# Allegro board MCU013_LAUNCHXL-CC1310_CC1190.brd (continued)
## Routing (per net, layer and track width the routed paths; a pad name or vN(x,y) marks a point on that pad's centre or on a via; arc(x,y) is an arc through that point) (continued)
DIO16_TDO: length 62.1
  TOP w0.15: 34.75,69.75 34.9,69.6 v1(34.9,68.7) U1.26 ; 34.75,69.75 34.75,75.8 35.12,76.17 35.12,76.45 35.45,76.78 35.45,77.5 ; 34.75,69.75 34.75,69.75 34.85,69.65 ; CR8.5 42.67,75.9 43.24,76.47 P5.6 43.24,78.45 42.39,79.3 39.5,79.3 37.7,77.5 35.45,77.5 ; v1(47.7,66.5) 47.7,56.7 46.5,55.5 46.5,49.03 45.7,48.22 R48.2 ; 35.45,77.5 35.44,77.5 P4.4
  L3 w0.15: v1(34.9,68.7) 38.6,68.7 40.8,66.5 v1(47.7,66.5)
DIO17_TDI: length 72.1
  TOP w0.15: R49.2 45.7,45.62 44.7,46.62 44.7,55.4 45.7,56.4 v1(45.7,66) ; v1(38.3,79.8) 38,80.1 33.26,80.1 P4.6 v1(31.78,77.42) ; CR8.3 39.7,74.4 40.9,75.6 43.16,75.6 44.51,76.95 P5.8 44.51,79.19 44,79.7 40.1,79.7 40,79.8 v1(39.6,79.8) ; U1.27 v1(34.4,68.22) 34.4,68.7 34.32,68.78 34.32,75.8 34.82,76.3 34.82,76.65 34.7,76.78 v1(34.7,77.42)
  L3 w0.15: v1(34.4,68.22) 38.47,68.22 40.7,66 v1(45.7,66) ; v1(38.3,79.8) v1(39.6,79.8) ; v1(31.78,77.42) v1(34.7,77.42)
DIO19_CTS: length 23.6
  TOP w0.15: 33.4,65.55 U1.29 v1(33.4,67.8) ; v1(46.55,65.5) 46.97,65.07 v1(46.97,61.2)
  L3 w0.15: v1(46.55,65.5) 40.78,65.5 38.47,67.8 v1(33.4,67.8) ; v1(46.97,61.2) 47.38,61.2 47.74,60.84 J2.7
DIO20_FLASH_CS: length 41.6
  TOP w0.15: v1(33.4,68.7) 32.9,68.2 32.9,66.58 U1.30 32.9,65.55 ; v1(44.8,67.7) v1(44.8,64.7) 44.8,60.75 40.45,56.4 39,56.4 38.3,55.7 38.3,53 38.7,52.6 R11.1 U4.1
  L3 w0.15: v1(33.4,68.7) 34.3,69.6 38.9,69.6 40.8,67.7 v1(44.8,67.7) ; J2.5 48.26,64.7 v1(44.8,64.7)
DIO21: length 62.6
  TOP w0.15: U1.31 32.4,66.5 32.6,66.71 32.6,69.69 32.4,69.9 32.4,74.5 31.9,75 9.6,75 2.7,68.1 2.7,67.85 2.7,67.85 2.7,51.3 3.32,50.68 J1.15
DIO22: length 50.6
  TOP w0.15: 32.3,68.43 32.3,66.83 31.9,66.43 U1.32 ; 32.3,68.43 32.3,69.57 32,69.87 32,73.45 31.05,74.4 10.2,74.4 3.3,67.5 3.3,61.38 J1.9 ; 32.3,68.43 32.3,68.43
DIO23_ANALOG: length 28.5
  TOP w0.15: 7.76,67.3 7.76,67.3 11.3,67.3 12.72,65.88 12.72,65.47 13.07,65.13 28.53,65.13 28.95,65.55 U1.36 ; 7.76,67.3 10.9,67.3 ; 7.76,67.3 J1.3
DIO24_ANALOG: length 30.7
  TOP w0.15: J1.11 7.6,56.98 7.6,64 8.43,64.82 U1.37
DIO25_ANALOG: length 20.6
  TOP w0.15: U1.38 9.87,64.32 J1.6
DIO26_ANALOG: length 22.2
  TOP w0.15: U1.39 10.78,63.82 10.05,63.1 10.05,61.97 J1.8
DIO27_ANALOG: length 24.1
  TOP w0.15: U1.40 10.95,63.32 10.6,62.98 10.6,59.98 J1.10
DIO28_CC1190_HGM: length 30.6
  TOP w0.15: J1.12 10.6,57.44 10.6,58.55 11,58.95 11,62.75 11.28,63.03 28.55,63.03 28.75,62.82 U1.41 ; R66.1 v1(11.9,57)
  L3 w0.15: J1.12 10.16,57 v1(11.9,57)
DIO29_CC1190_LNA_EN: length 32.5
  TOP w0.15: J1.14 10.9,55.2 10.9,58.42 11.39,58.91 11.39,62.54 11.57,62.72 28,62.72 28.4,62.32 U1.42 ; v1(11.78,54.15) R71.1
  L3 w0.15: v1(11.78,54.15) 10.88,54.15 9.95,53.22 J1.14
DIO30_CC1190_PA_EN: length 57.3
  TOP w0.15: U1.43 28.48,61.82 27.9,62.4 27.8,62.4 27.78,62.43 23.52,62.43 23.5,62.4 18.4,62.4 ; 18.4,62.4 v1(18.4,56.6) ; 18.4,62.4 12,62.4 11.69,62.09 11.69,58.79 11.35,58.45 11.35,53.11 J1.16 ; v1(33.8,45.05) 33.8,45.05 34.1,44.75 R81.1
  L3 w0.15: v1(33.8,45.05) 30.95,47.9 27.1,47.9 v1(18.4,56.6)
IRSTN: length 16.5
  TOP w0.15: v1(5.3,109.5) 5.3,107.9 v1(3.5,106.1) ; v1(6.82,109.5) 9.5,109.5 11.2,107.8 11.2,105.5 11.8,104.9 R20.2 14.4,104.9
  L3 w0.15: v1(5.3,109.5) v1(6.82,109.5)
ITCK: length 12.2
  TOP w0.15: U5.100 2,100.6 0.8,101.8 0.8,108.7 v1(2.1,110)
ITDI: length 10.1
  TOP w0.15: v1(3.38,108.7) 2.8,108.12 2.8,106.5 1.44,105.14 1.44,102.01 2.05,101.4 U5.98
ITDO: length 13.2
  TOP w0.15: v1(3.4,111.3) 4.8,109.9 4.8,108.08 1.74,105.01 1.74,102.14 2.08,101.8 U5.97
ITMS: length 9
  TOP w0.15: v1(2.1,107.5) 1.14,106.54 1.14,101.89 2.03,101 3.8,101
LP_RESET: length 17.9
  TOP w0.15: R51.1 51.1,72.3 54.4,69 54.4,60.58 J2.10
USB_DM: length 14.1
  TOP w0.15: v1(8.7,110.9) 7.3,110.9 6.4,110 6.4,104.1 6.5,104 U5.93 ; CR6.5 10.8,112.85 v1(10.75,112.9) J6.2
  L3 w0.15: v1(8.7,110.9) 8.99,111.19 9.06,111.19 10.75,112.88 v1(10.75,112.9)
USB_DP: length 15.5
  TOP w0.15: U5.94 6.1,110.12 7.36,111.38 8.91,111.38 v1(9.4,110.9) ; 11.3,112.19 11.3,112.8 v1(11.4,112.9) J6.3
  L3 w0.15: v1(9.4,110.9) v1(11.4,112.9)
USB_ID: length 14.1
  TOP w0.15: J6.4 v1(12.05,112.9) ; R19.1 5.6,106.68 5.8,106.88 5.8,110.25 7.25,111.7 9.4,111.7 10.1,111 v1(10.8,111) CR6.2
  L3 w0.15: v1(12.05,112.9) 10.8,111.65 v1(10.8,111)
USB_VBUS: length 55.8
  TOP w0.15: R22.2 4.38,86.87 v1(4.6,87.1) ; U7.8 v1(14.7,110.58) ; R152.1 3.69,104.7 3.2,104.21 3.2,103.9 v1(2.6,103.3)
  TOP w0.3: J6.1 v1(10.1,112.9) 10.1,112.87 10.3,112.67 CR6.6 ; C48.1 12.2,111.08 11.7,110.58 U7.1 U7.2
  TOP w0.5: v1(12.2,111.9) C48.1
  L3 w0.5: v1(2.6,103.3) 0.85,103.3 0.75,103.4 ; P4.19 11.86,83.3 7.6,83.3 4.6,86.3 v1(4.6,87.1) 0.75,90.95 0.75,103.4 ; 0.75,103.4 0.75,108.24 1.85,109.34 3.94,109.34 4.7,110.1 11.22,110.1
V-SENSE: length 40.2
  TOP w0.15: v1(21.7,85.1) C53.1 U8.2 ; v1(29.9,85.1) C57.1 U9.2 ; v1(25.7,85.1) C55.1 U10.2
  TOP w0.3: v1(29.9,85.1) 36.7,85.1 37.6,86 38.45,86 38.55,85.9 ; P10.2 48.3,82.76 48.3,84.7 46.47,86.53 P7.1 45.76,87.28 44.94,88.1 39.8,88.1 38.55,86.85 38.55,85.9 ; 38.55,85.9 CR7.8
  L3 w0.3: v1(21.7,85.1) v1(25.7,85.1) 26.99,85.1 27.09,85 27.51,85 27.72,85.21 29.09,85.21 29.2,85.1 v1(29.9,85.1)
XDS_RESET: length 11.5
  TOP w0.15: U10.1 23.78,84.7 23.51,84.97 U10.6 v1(23.51,87.7) ; v1(22.8,89.7) 21.8,90.7 21.8,91.69 21.3,92.19 R58.1 U5.40
  L3 w0.15: v1(23.51,87.7) 23.79,87.99 23.79,89.4 23.5,89.7 v1(22.8,89.7)
XDS_RESET_LS: length 62.5
  TOP w0.15: U10.15 23.51,83.49 v1(24,83) 24,82.6 24.16,82.44 P4.11 ; 17.6,114.3 R57.2 v1(17,114.3) ; v1(34.6,84.6) 37.32,84.6 37.1,84.38 37.1,83.7 38.87,81.93 40.68,81.93
  TOP w0.3: 37.32,84.6 CR7.2
  L3 w0.15: v1(34.6,84.6) 31.1,84.6 ; 31.1,84.6 30.7,85 30.7,86.1 23.74,93.06 23.74,113.34 22.78,114.3 v1(17,114.3) ; 31.1,84.6 29.7,83.2 27.03,83.2 26.83,83 26.47,83 26.47,83 v1(24,83)
XDS_RX: length 3.1
  TOP w0.15: U8.8 18.71,86.84 19.2,87.33 U5.33
XDS_RX_LS: length 10.6
  TOP w0.15: U8.13 18.71,82.71 17.9,81.9 17.9,80.5 18.5,79.9 21.2,79.9 21.6,80.3 21.6,81.16 P4.13 21.62,82.45 R61.2
XDS_SWO: length 7.2
  TOP w0.15: U8.9 18.5,85.9 18.1,86.3 18.1,88.75 17.95,88.9 15.05,88.9 14.9,88.75 U5.25
XDS_SWO_LS: length 24.7
  TOP w0.15: 35.5,83.2 R62.2 34.8,83.2 ; 35.5,83.2 35.5,83.95 35.35,84.1 v1(32.5,84.1) ; 35.5,83.2 35.5,82.52 P4.1 ; U8.12 v1(17.8,84.7)
  L3 w0.15: v1(32.5,84.1) 31.21,82.81 27.11,82.81 26.8,82.5 19,82.5 17.8,83.7 v1(17.8,84.7)
XDS_TCK: length 10.4
  TOP w0.15: U5.35 20.15,90.2 20.7,89.65 v1(20.7,89.2) ; v1(23.3,89.2) 23.69,88.81 25.78,88.81 27.51,87.09 U9.6
  L3 w0.15: v1(23.3,89.2) v1(20.7,89.2)
XDS_TCK_LS: length 29.2
  TOP w0.15: U9.15 27.51,83.55 28.52,82.54 28.52,81.89 P4.7 ; CR7.6 43.9,84.6 44.49,84.01 P7.4 44.49,80.55 43.94,80 40.5,80 40.2,80.3 39.5,80.3 38.57,79.38 38.12,79.38 37.83,79.67 v1(35.8,79.67)
  L3 w0.15: v1(35.8,79.67) 30.73,79.67 P4.7
XDS_TDI: length 10.2
  TOP w0.15: U5.38 20.4,91.4 23.3,88.5 25.66,88.5 27.11,87.05 U9.7
XDS_TDI_LS: length 26.6
  TOP w0.15: v1(39.64,81.16) 40.12,80.68 41.45,80.68 41.95,81.18 P7.8 41.95,82.68 41.37,83.26 40.44,83.26 40.08,82.9 38.53,82.9 37.8,83.62 CR7.3 ; P4.5 30.42,79.8 29.12,79.8 28.19,80.73 28.19,82.31 27.11,83.39 U9.14
  L3 w0.15: P4.5 32.84,80.1 37.29,80.1 38.35,81.16 v1(39.64,81.16)
XDS_TDO: length 10.1
  TOP w0.15: U9.9 26.3,86.1 26.3,87.3 25.4,88.2 23.1,88.2 20.3,91 19.2,91
XDS_TDO_LS: length 25.5
  TOP w0.15: U9.12 26.27,84.7 26.03,84.46 26.03,83.37 26.4,83 26.85,83 v1(27.77,82.08) ; R63.2 43.22,80.61 P7.6 43.22,83.58 42.7,84.1 v1(40.1,84.1) CR7.5
  L3 w0.15: v1(40.1,84.1) 40.1,83.7 38.8,82.4 35.56,82.4 P4.3 33.27,82.21 28.29,82.21 28.17,82.08 v1(27.77,82.08)
XDS_TMS: length 6.1
  TOP w0.15: U5.36 20.2,90.6 22.71,88.09 U10.8
XDS_TMS_DIR: length 12.8
  TOP w0.15: v1(18.6,87.5) 18.6,88.68 18.07,89.2 14.85,89.2 14.5,88.85 U5.24 ; U10.5 23.91,87.11 v1(24,87.2)
  L3 w0.15: v1(18.6,87.5) 18.9,87.2 v1(24,87.2)
XDS_TMS_LS: length 33.5
  TOP w0.15: U10.13 22.71,81.13 23.73,80.11 25.65,80.11 P4.9 ; R65.2 46.25,81.92 46.24,81.93 P7.2 45.76,84.14 44.8,85.1 v1(40.1,85.1) CR7.7
  L3 w0.15: v1(40.1,85.1) 36.1,85.1 35.18,84.18 33.28,84.18 31.61,82.51 27.41,82.51 26.7,81.8 P4.9
XDS_TX: length 4.5
  TOP w0.15: U8.6 19.51,88.51 20.2,89.2 20.2,89.65 20.05,89.8 U5.34
XDS_TX_LS: length 3.1
  TOP w0.15: P4.15 19.08,82.19 19.51,82.62 U8.15
XDS_VCC: length 87
  TOP w0.15: U9.3 U9.4 C56.1 ; v1(16.6,109.5) C47.1 17.48,108.9 R33.2 ; v1(8.9,85.1) R18.2 8.9,85.7 8.8,85.6 C42.1 ; v1(17.1,106.65) 17.12,106.62 R17.2 17.11,105.9 16.7,105.49 16.7,105.39 16.21,104.9 C38.1 ; v1(25.7,85.9) C54.1 U10.4 U10.3 ; v1(21.7,85.9) C52.1 U8.4 U8.3 ; v1(20.7,91.7) 21.13,91.28 R58.2 ; v1(22.5,99.7) R30.2 21.9,99.7 ; 2.4,100.2 C37.1
  TOP w0.2: 15.5,86.5 C35.1 v1(15.5,85.6) ; 15.5,86.5 15.3,86.7 U5.26 ; 15.5,86.5 16.1,87.1 U5.28 ; v1(20.7,91.7) 20.6,91.8 U5.39 ; C42.1 C41.1 8.1,86.7 U5.8 U5.7 ; v1(1.65,95.5) C36.1 2.4,95.4 U5.113 ; U5.16 11.3,87 v1(11.5,86.8) ; U5.52 U5.51 C39.1 C40.1 v1(22.3,96.6) ; v1(21.9,103) R39.1 R27.1 ; 19.2,95 v1(20.26,95) ; U5.79 v1(12.1,104.36) ; U5.101 2.4,100.2 ; v1(20.6,104.9) R31.2 20,104.9 ; 16.2,104.94 C38.1 16.2,104.45 16.1,104.35 U5.69 ; U5.90 7.7,104.3 v1(7.6,104.4) ; C37.1 v1(1.75,100) ; U5.122 v1(2.74,91.8)
  TOP w0.3: v1(11.7,105.8) v1(11.7,106.3) C49.1 U7.4 U7.3 ; C56.1 v1(29.9,85.9) 36.8,85.9 39.5,88.6 48.8,88.6 49.9,87.5 P10.1
  TOP w0.5: P4.17 15.5,82.2 v1(15.5,85) v1(15.5,85.6)
  L3 w0.15: v1(16.6,109.5) 16.6,107.1
  L3 w0.3: 17.6,87.4 19.1,85.9 v1(21.7,85.9) v1(25.7,85.9) 26.99,85.9 27.09,86 27.5,86 27.6,85.9 v1(29.9,85.9)
  vias: v1(2,106.4)
N949215: length 3.8
  TOP w0.15: U5.70 15.7,104.4 R20.1 R21.1 R17.1
N949243: length 2.1
  TOP w0.15: R30.1 21.09,99.7 20.59,100.2 U5.60
N949263: length 2.9
  TOP w0.15: R33.1 17.48,107.98 C47.2 R34.2 15.7,108 15.55,108.15 U7.5 14.7,108.15
N949375: length 2.3
  TOP w0.15: U5.59 20.15,99.8 20.57,99.38 20.57,99.19 20.96,98.8 R28.2
N949517: length 2.3
  TOP w0.15: U5.1 R22.1 R24.1
N949687: length 6.3
  TOP w0.15: 7.9,108.9 7.9,108.5 7.3,107.9 Y3.3 7.3,107.6 8.18,106.72 8.18,104.33 8.1,104.25 U5.89
  TOP w0.2: C34.1 7.9,108.9
N949695: length 4.1
  TOP w0.15: U5.88 8.5,105 Y3.1 9,105.7 9.8,106.5 C33.1
N950083: length 5.9
  TOP w0.15: U5.9 8.5,86.9 R18.1 C32.1 C50.1 9.91,85.6 10.5,85 U6.3
N950235: length 2.1
  TOP w0.15: U5.95 5.7,104.48 5.6,104.57 R19.2 5.6,105.4
N951001: length 2.2
  TOP w0.15: R39.2 20.96,102.4 19.96,101.4 U5.63
N951013: length 1.9
  TOP w0.15: U5.61 R29.1
N951017: length 2.1
  TOP w0.15: R27.2 20.98,101.38 20.59,101 19.2,101
N952443: length 3.9
  TOP w0.15: 18.33,104.9 17.73,104.3 16.65,104.3 16.5,104.15 U5.68 ; 18.33,104.9 R31.1 ; 18.33,104.9 C46.1
N1004371: length 7.2
  TOP w0.15: U5.3 6.1,88.61 5.81,88.9 4.93,88.9 2.62,86.6 1.66,86.6 1,87.26 R23.2
N1004534: length 6.2
  TOP w0.15: U5.4 6.5,88.85 6.15,89.2 4.8,89.2 2.88,87.28 R25.2
N1013277: length 7
  TOP w0.15: Y2.3 23.27,59.83 24.2,58.9 26.3,58.9 27.21,59.81 27.97,59.81 28.49,60.32 U1.46
N1013919: length 1
  TOP w0.3: C15.1 30.65,55.95 30.6,56 TR1.1
N1014101: length 9.2
  TOP w0.15: U1.4 31.4,57.95 32,57.35 32,56.3 34.46,53.84 34.46,53.44 35.1,52.8 Y1.1 C17.1
N1014113: length 7.1
  TOP w0.15: U1.5 31.9,57.93 32.8,57.03 32.8,56.6 34.1,55.3 Y1.2 C18.1
N1018952: length 5.2
  TOP w0.15: U1.47 28.53,59.82 28.1,59.4 27.43,59.4 25.73,57.7 Y2.1 25,57.8
N1031635: length 4.4
  TOP w0.15: v1(15.2,113.6) 15.7,113.1 R32.2
  TOP w0.3: 8.05,112.95 v1(7.7,113.3) ; 8.1,112.95 9.4,112.95 9.55,112.8 9.55,112.2 10.15,111.6 CR6.1 10.35,111.6
  vias: v1(7.3,114.6) v1(15.6,114.5)
N1105722: length 1.2
  TOP w0.15: R15.1 CR1.2
N1105771: length 1.2
  TOP w0.15: R14.1 CR2.2
N1105824: length 4.4
  TOP w0.15: R14.2 17.1,54.09 17.15,54.14 P6.1
N1106228: length 4.4
  TOP w0.15: P6.3 19.69,56.97 19.7,56.96 R15.2
N1176544: length 2.3
  TOP w0.15: R46.1 48.53,53.2 48.56,53.22 J2.13
N1176548: length 2.3
  TOP w0.15: R47.1 48.53,50.7 48.56,50.68 J2.15
N1176568: length 2.3
  TOP w0.15: R48.1 48.5,48.2 48.56,48.14 J2.17
N1177007: length 2.3
  TOP w0.15: R49.1 J2.19
N1288065: length 2.2
  TOP w0.15: SW2.3 R55.1
N1288098: length 1.5
  TOP w0.15: R56.1 4.68,72.7 4.65,72.72 SW1.4 3.8,72.72
N1384129: length 4.7
  TOP w0.15: R57.1 19.7,115.6 SW3.3
N1393569: length 1.5
  TOP w0.3: U1.23 36.56,64.32 37.2,64.96 C19.1
N1442334: length 0.8
  TOP w0.15: R59.1 41.2,51.9 U4.3
N1442341: length 0.9
  TOP w0.3: R60.1 40.7,55.5 U4.7
N1462615: length 2.2
  TOP w0.15: U11.8 33.47,43.38 33.52,43.33 R81.2
N1462623: length 26.4
  TOP w0.15: v1(32.8,42.75) 32.78,42.72 31.93,42.72 ; v1(14.5,52.85) 14.22,53.13 14.22,54.02 14.09,54.15 R71.2
  L3 w0.15: v1(14.5,52.85) 16.55,50.8 22.7,50.8 26.4,47.1 30.4,47.1 32.8,44.7 v1(32.8,42.75)
N1462627: length 4
  TOP w0.3: 31.8,38.95 C214.2 31.8,39.85 ; 31.8,39.85 31.8,39.95 32.38,40.53 C213.2 ; 31.8,39.85 31.42,39.85 31.05,40.22 U11.4
N1462755: length 3.9
  TOP w0.3: L25.1 C215.1 ; U11.2 29.75,39.3 L21.2
  TOP w0.4: L21.2 29.7,39.05 C215.1
N1462771: length 2.7
  TOP w0.3: L131.1 26.35,43.95 26.37,43.93 C131.2 26.9,43.91 27.44,43.38 U11.13
N1462879: length 1.5
  TOP w0.3: U11.16 27.38,41.43 L161.1
N1462923: length 1.1
  TOP w0.4: C210.1 L25.2 28.5,37.05
N1463021: length 1.1
  TOP w0.4: L26.2 31.8,37.13 C214.1 31.78,38.03
N1463025: length 4.5
  TOP w0.4: C24.1 L27.1 29.68,34.87 C212.2 29.7,35.97 C215.2 29.7,37.05 L26.1 30.9,37.05
N1463037: length 1.4
  TOP w0.3: C213.1 33.28,41.43 U11.5
N1463305: length 5.7
  TOP w0.4: C24.2 L27.2 30.68,33.93 C25.1 32.6,33.95 32.9,33.65 32.9,33 L24.1
N1463467: length 3.9
  TOP w0.25: R154.2 30.65,49.17 C219.2
  TOP w0.3: R155.1 L111.2 29.24,50.3 29.79,49.75 30.06,49.75 30.61,49.2 R154.2
N1463499: length 2.3
  TOP w0.3: C111.1 L111.1 FL2.5
N1463655: length 1.5
  TOP w0.3: U11.15 27.53,42.07 27.4,41.95 R151.2 26.8,41.95
N1486885: length 2.8
  TOP w0.15: U5.96 5.3,104.49 5.09,104.7 R152.2 4.62,105.48 C59.1
N1492721: length 7.1
  TOP w0.4: A1.1 A2.1 30.4,27.47 ; L24.2 30.4,30.5 30.4,27.47 ; 30.4,27.47 R158.2
N1607579: length 2.5
  TOP w0.25: C218.2 R154.1
  TOP w0.3: R154.1 R156.1
N1607593: length 3.1
  TOP w0.25: C218.1 29.7,46.79 29.75,46.74 U11.11
N1607716: length 1.4
  TOP w0.3: R141.1 27.12,42.72 28.22,42.72
N1608859: length 4.3
  TOP w0.4: P12.1 40.85,26.15 39.5,27.5 R13.1
N1608868: length 11.4
  TOP w0.4: R157.1 37.75,33.5 42.15,37.9 P11.1
N1608876: length 6.4
  TOP w0.4: R157.2 37.17,27.48 37.15,27.5 R158.1
N1616867: length 2.5
  TOP w0.4: A2.2 A3.1 28.85,26.1 ANT1.1
N1639516: length 1.2
  TOP w0.25: U1.1 29.9,58 29.78,57.88 TR1.4
N1639598: length 1.2
  TOP w0.25: TR1.3 30.6,57.8 30.4,58 U1.2
N1639697: length 2
  TOP w0.25: U1.3 30.9,58.07 31,57.97 31,57.84 31.1,57.74 31.1,57.26 30.84,57 TR1.2
N1666431: length 3.2
  TOP w0.25: U11.10 30.4,46.54 30.65,46.79 C219.1
N10367920: length 1
  TOP w0.15: R25.1 CR5.2
N10368080: length 1
  TOP w0.15: R23.1 CR4.2
N14625751: length 29
  TOP w0.15: v1(33.5,42.35) 33.1,42.35 32.82,42.07 U11.6 ; R66.2 v1(14.7,57)
  L3 w0.15: v1(14.7,57) 14.99,56.72 15.59,56.72 18,54.3 20.1,54.3 26.9,47.5 30.75,47.5 33.5,44.75 v1(33.5,42.35)

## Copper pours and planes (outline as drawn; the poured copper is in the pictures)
GND on TOP: 0.5,114.3 0.5,117.84 0.78,118.52 1.46,118.8 6.5,118.8 6.5,117.6 6.6,117.6 6.6,114.3
GND on TOP: 42.15,20.65 36.8,26 32.9,26 32.9,27 39.25,27 40.5,25.75 40.95,25.75 40.95,26.8 39.75,28 38.25,28 38.25,33.35 42.3,37.4 42.7,37.4 42.7,38.4 41.9,38.4 37.25,33.75 37.25,28 30.9,28 30.9,29.7 35.65,29.7 35.65,46.05 19.35,46.05 19.35,29.7 29.9,29.7 29.9,27 27,27 27,26 0.5,26 0.5,68.5 0.76,70 1.49,71.34 2.7,74.8 1.49,78.26 0.97,79.09 0.64,80 0.67,80 0.5,81.3 0.5,117.84 0.78,118.52 1.46,118.8 6.5,118.8 6.5,115 6.5,112.7 9.2,112.7 9.2,113.2 8.3,113.2 8.1,113.4 8.1,115.5 10,115.5 10,117.6 12.8,117.6 12.8,115.5 14.5,115.5 14.5,112.7 16.3,112.7 16.3,118.8 57.04,118.8 57.72,118.52 58,117.84 58,104.17 58,89.19 58,80.7 57.85,80 57.86,80 57.53,79.08 57.01,78.26 55.8,74.8 57.01,71.34 57.74,70 58,68.5 58,35.65 53.65,35.65 53.65,33.85 50.95,33.85 50.95,29.8 44.6,29.8 44.6,22.5 50.95,22.5 50.95,20.65 ; 26 cut-outs
GND on TOP: 19.6,30.05 19.6,45.75 35.1,45.75 35.1,30.05 30.9,30.05 30.9,30.25 33.5,32.85 33.5,33.95 32.8,34.65 30.3,34.65 30.3,35.35 31.2,35.35 31.2,36.45 32.4,36.45 32.4,39.55 31.2,39.55 31.2,37.65 30.3,37.65 30.3,39.95 27.4,39.95 27.4,39.75 27.2,39.75 27.2,38.55 27.4,38.55 27.4,38.45 27.9,38.45 27.9,36.55 27,36.55 27,35.35 28,35.35 28,33.35 30.1,33.35 30.1,32.45 31.3,32.45 31.3,33.35 32.6,33.35 29.9,30.65 29.9,30.05
GND on BOTTOM: 42.1,20.7 36.8,26 0.5,26 0.5,68.5 0.76,70 1.49,71.34 2.7,74.8 1.49,78.26 1.33,78.48 1.18,78.7 0.67,79.85 0.5,81.1 0.5,81.29 0.5,81.3 0.5,117.84 0.78,118.52 1.46,118.8 6.5,118.8 6.5,117.6 8.1,117.6 8.1,115.5 10,115.5 10,117.6 12.8,117.6 12.8,115.5 14.7,115.5 14.7,117.6 16.3,117.6 16.3,118.8 57.04,118.8 57.72,118.52 58,117.84 58,117.6 58,81.8 58,81.1 58,81.09 57.82,79.85 57.32,78.7 57.17,78.48 57.01,78.26 55.8,74.8 57.01,71.34 57.74,70 58,68.5 58,35.7 53.6,35.7 53.6,33.9 50.9,33.9 50.9,29.8 44.6,29.8 44.6,22.5 50.9,22.5 50.9,20.7
GND on BOTTOM: 0.51,114.29 0.51,117.83 0.79,118.51 1.47,118.79 5.11,118.79 5.11,114.29
GND on BOTTOM: 53.27,114.21 53.27,118.81 57.01,118.81 57.69,118.53 57.97,117.85 57.97,114.21
GND on L2: 42.15,20.65 36.8,26 0.5,26 0.5,68.5 0.76,70 1.49,71.34 2.7,74.8 1.49,78.26 1.27,78.57 1.07,78.9 0.64,79.96 0.5,81.1 0.5,81.2 0.51,81.2 0.5,81.3 0.5,117.84 0.78,118.52 1.46,118.8 6.5,118.8 6.5,117.6 8.1,117.6 8.1,115.5 10,115.5 10,117.6 12.8,117.6 12.8,115.5 14.7,115.5 14.7,117.6 16.3,117.6 16.3,118.8 57.04,118.8 57.72,118.52 58,117.84 58,117.6 58,81.3 58,81.1 57.85,79.96 57.43,78.9 57.23,78.57 57.01,78.26 55.8,74.8 57.01,71.34 57.74,70 58,68.5 58,35.65 53.65,35.65 53.65,33.85 50.95,33.85 50.95,29.8 44.6,29.8 44.6,22.5 50.95,22.5 50.95,20.65 ; 2 cut-outs
CC1190_VDD on L3: 14.8,44.3 14.8,42.8 24.4,42.8 24.4,44.3
CC1190_VDD on L3: 22.5,45.6 22.5,38.7 24.4,38.7 24.4,45.6
USB_VBUS on L3: 10.3,113.9 12.4,113.9 14.9,111.4 14.9,110.3 14.3,109.7 8.9,109.7 7.9,110.7 7.9,111.5
XDS_VCC on L3: 3.4,108.2 21.1,108.2 23.1,106.2 23.1,92.3 14.9,84.1 7.5,84.1 1.1,90.5 1.1,105.9
N1031635 on TOP: 6.8,112.9 6.8,117.6 8.1,117.6 8.1,115.5 10,115.5 10,117.6 12.8,117.6 12.8,115.7 14.5,115.7 14.5,115.1 14.7,115.1 14.7,115.7 14.7,117.6 16,117.6 16,112.9 ; 1 cut-out
N1031635 on BOTTOM, L2: 6.8,112.9 6.8,117.6 8.1,117.6 8.1,115.5 10,115.5 10,117.6 12.8,117.6 12.8,115.5 14.7,115.5 14.7,117.6 16,117.6 16,112.9
N1616867 on TOP (solid shape): 29.85,15.75 11.85,15.75 11.85,12.75 47.85,12.75 47.85,5.75 11.85,5.75 11.85,2.75 47.85,2.75 47.85,0.75 9.85,0.75 9.85,7.75 45.85,7.75 45.85,10.75 9.85,10.75 9.85,17.75 27.85,17.75 27.85,25.75 29.85,25.75

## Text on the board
Ref Des/Silkscreen Bottom: J1 | 1 | 10 | 21 | 30 | J3 | J4 | 31 | 40 | 11 | 20 | J2 | DIO23 | DIO3 | DIO2 | DIO22 | DIO24 | DIO0 | DIO1 | DIO25 | DIO27 | DIO28 | DIO29 | DIO30 | DIO26 | DIO7 | DIO6 | DIO20 | DIO19 | DIO18 | BPRST | NC | DIO9 | DIO8 | DIO12 | DIO11 | LPRST | DIO13 | DIO14 | DIO15 | DIO10 | DIO21 | DIO4 | DIO5 | TMS | TCK | DIO16 | DIO17
User.Comments: RED
Ref Des/Silkscreen Top: J1 | 10 | 1 | 21 | 30 | J3 | J4 | 40 | 31 | 20 | 11 | J2 | DIO3 | DIO2 | DIO23 | DIO22 | DIO24 | BTN-1 | DIO13 | DIO29 | DIO30 | DIO27 | DIO28 | DIO6 | DIO1 | DIO26 | DIO25 | Red: | LEDs | Green: | DIO7 | CC-ANTENNA-DK | Mount for: | CC1310 In | DIO20 | DIO19 | DIO18 | BPRST | VSENSE | BTN-2 | DIO14 | LP | BP | Extern. | Pwr. | XDS110 | Power | NC | DIO12 | DIO11 | LPRST | DIO9 | DIO8 | DIO15 | DIO10 | DIO21 | DIO4 | DIO5 | DIO17 | DIO16 | TMS | TCK | RXD<< | TXD>> | RESET | Reset | TDI | TDO | SWO>> | Rev: 1.3 MCU013 | LAUNCHXL-CC13-90
XSECTION_CHART: *  SURFACE - AIR 0 MM | L1: TOP CONDUCTOR - COPPER 0.035 MM | *  DIELECTRIC - FR-4 0.4 MM | L2: L2 PLANE - COPPER 0.035 MM | *  DIELECTRIC - FR-4 0.66 MM | L3: L3 PLANE - COPPER 0.035 MM | L4: BOTTOM CONDUCTOR - COPPER 0.035 MM | DESIGN CROSS SECTION CHART | ___________________________ | TOTAL THICKNESS 1.6 MM
DIMENSION: Milling tool 0.5 mm
DISPLAY_BOTTOM: FIGURE | FINISHED_SIZE | 0.2 | 0.201 | 1.05 | 1.1 | 3.2 | 0.899 | 1.001 | 3.0 | 1.3x0.6 | DRILL CHART: TOP to BOTTOM | ALL UNITS ARE IN MILLIMETERS | ROTATION | - | 90.000 | PLATED | NON-PLATED | QTY | 679 | 28 | 75 | 1 | 2 | 6 | 3 | 4
